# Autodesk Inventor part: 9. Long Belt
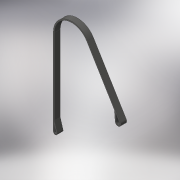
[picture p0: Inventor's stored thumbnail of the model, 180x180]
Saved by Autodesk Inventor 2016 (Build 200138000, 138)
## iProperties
Created: 2016-01
Part Number: 9. Long Belt
Material: Generic
Document SubType Name: Modeling
Designer: Black Falcon
Density: 1 g/cm^3
Appearance: Rubber - Black - Version 1.1
Author: Black Falcon
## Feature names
1. Sweep1
2. Extrusion1
3. Extrusion2
## Parameters: d0 = 76.2 mm, d1 = 7.62 mm, d2 = 101.6 mm, d3 = 101.6 mm, d4 = 12.7 mm, d5 = 2.54 mm, d6 = 0, d7 = 0, d8 = 25.4 mm, d9 = 0, d10 = 3.81 mm, d11 = 25.4 mm, d12 = 0
